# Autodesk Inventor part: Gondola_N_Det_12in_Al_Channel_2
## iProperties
Shininess: 64.0
Length Units: 11272
Angle Units: 11279
Time Units: 11290
Mass Units: 11286
Length Display Precision: 3
Angle Display Precision: 2
Compacted: True
Part Number: Gondola_N_Det_12in_Al_Channel_2
Document SubType Name: Modeling
Created: 2004-12
Designer: John Blackburn
Material: Aluminum-6061
Description: AL. Assoc. 8" 6061-T6 Channel
Manufacturer: Standard
Standards Organization: Custom
Density: 0.0
Volumn: 0.0
Area: 0.0
PropertySet Name: Model Information
Control State: 0
Master: False
Checked Out: False
Author: John Blackburn
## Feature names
1. Extrusion1
2. Hole1
3. Hole2
4. Hole3
5. Hole4
6. Hole5
7. Hole6
